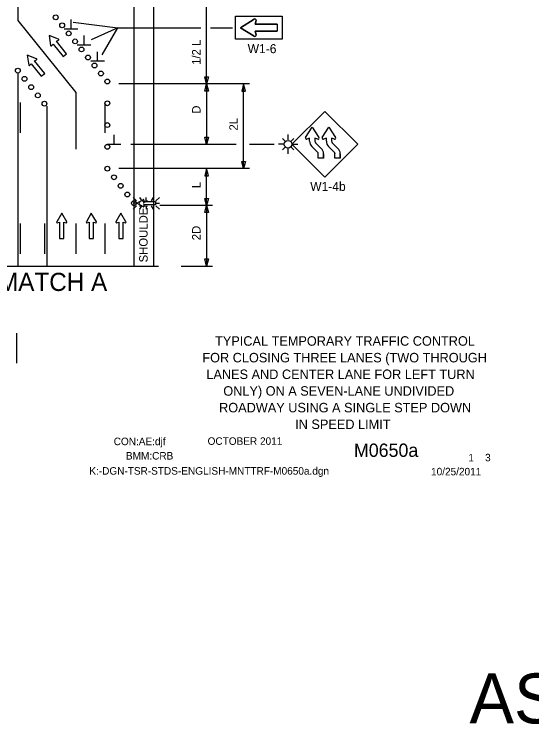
# Model space of a CAD drawing. Extents: x 16544 to 19504, y 5662 to 6909.
# Drawn here: x 17009 to 17436, y 5716 to 6314 of the extents above; entities that cross this region are included whole.
import ezdxf

# ---------------------------------------------------------------- set-up
doc = ezdxf.new("R2010")
doc.units = 0
for name, color, linetype in [('ALI_LEGAL_EX', 7, 'Continuous'), ('BORDER', 7, 'Continuous'), ('BORDER_SIGNAL_WO', 7, 'Continuous'), ('MT_SCRATCH_LEVEL_E', 7, 'Continuous'), ('PAVT_EDGE_EX', 7, 'Continuous'), ('TRAFFIC_SIGNS_PR', 7, 'Continuous'), ('TYPICAL_TEXT_DIMEN_PR', 7, 'Continuous')]:
    doc.layers.add(name, color=color, linetype=linetype)

msp = doc.modelspace()

# ---------------------------------------------------------------- linework, layer by layer
at = {"layer": 'ALI_LEGAL_EX'}
for points in [[(17013.46, 6241.23), (17013.46, 6216.23)], [(17083.46, 6241.23), (17083.46, 6216.23)], [(17013.46, 6141.23), (17013.46, 6116.23)], [(17033.46, 6141.23), (17033.46, 6116.23)], [(17059.46, 6141.23), (17059.46, 6116.23)], [(17083.46, 6141.23), (17083.46, 6116.23)]]:
    msp.add_lwpolyline(points, dxfattribs=at)
at = {"layer": 'MT_SCRATCH_LEVEL_E'}
for p, q in [((17037.27, 6296.58), (17038.61, 6288.36)), ((17045.04, 6293.54), (17037.27, 6296.58)), ((17037.27, 6296.58), (17038.61, 6288.36)), ((17045.04, 6293.54), (17037.27, 6296.58)), ((17039.41, 6288.13), (17040.6, 6289.49)), ((17039.41, 6288.13), (17040.6, 6289.49)), ((17040.6, 6289.49), (17048.91, 6279.16)), ((17040.6, 6289.49), (17048.91, 6279.16)), ((17043.51, 6291.83), (17045.09, 6292.7)), ((17043.51, 6291.83), (17045.09, 6292.7)), ((17051.83, 6281.51), (17043.51, 6291.83)), ((17051.83, 6281.51), (17043.51, 6291.83)), ((17019.13, 6280.37), (17020.47, 6272.15)), ((17026.9, 6277.33), (17019.13, 6280.37)), ((17019.13, 6280.37), (17020.47, 6272.15)), ((17026.9, 6277.33), (17019.13, 6280.37)), ((17025.37, 6275.62), (17026.95, 6276.49)), ((17025.37, 6275.62), (17026.95, 6276.49)), ((17048.91, 6279.16), (17051.83, 6281.51)), ((17048.91, 6279.16), (17051.83, 6281.51)), ((17021.27, 6271.92), (17022.46, 6273.28)), ((17021.27, 6271.92), (17022.46, 6273.28)), ((17022.46, 6273.28), (17030.77, 6262.95)), ((17022.46, 6273.28), (17030.77, 6262.95)), ((17033.69, 6265.3), (17025.37, 6275.62)), ((17033.69, 6265.3), (17025.37, 6275.62)), ((17030.77, 6262.95), (17033.69, 6265.3)), ((17030.77, 6262.95), (17033.69, 6265.3)), ((17047.7, 6149.79), (17043.59, 6142.55)), ((17047.7, 6149.79), (17043.59, 6142.55)), ((17051.85, 6142.55), (17047.7, 6149.79)), ((17051.85, 6142.55), (17047.7, 6149.79)), ((17072.2, 6149.79), (17068.09, 6142.55)), ((17072.2, 6149.79), (17068.09, 6142.55)), ((17076.35, 6142.55), (17072.2, 6149.79)), ((17076.35, 6142.55), (17072.2, 6149.79)), ((17096.7, 6149.79), (17092.59, 6142.55)), ((17096.7, 6149.79), (17092.59, 6142.55)), ((17100.84, 6142.55), (17096.7, 6149.79)), ((17100.84, 6142.55), (17096.7, 6149.79)), ((17044.07, 6141.87), (17045.85, 6142.19)), ((17044.07, 6141.87), (17045.85, 6142.19)), ((17045.85, 6142.19), (17045.85, 6128.93)), ((17045.85, 6142.19), (17045.85, 6128.93)), ((17049.59, 6128.93), (17049.59, 6142.19)), ((17049.59, 6142.19), (17051.37, 6141.87)), ((17049.59, 6128.93), (17049.59, 6142.19)), ((17049.59, 6142.19), (17051.37, 6141.87)), ((17068.57, 6141.87), (17070.35, 6142.19)), ((17068.57, 6141.87), (17070.35, 6142.19)), ((17070.35, 6142.19), (17070.35, 6128.93)), ((17070.35, 6142.19), (17070.35, 6128.93)), ((17074.09, 6128.93), (17074.09, 6142.19)), ((17074.09, 6142.19), (17075.87, 6141.87)), ((17074.09, 6128.93), (17074.09, 6142.19)), ((17074.09, 6142.19), (17075.87, 6141.87)), ((17093.07, 6141.87), (17094.85, 6142.19)), ((17093.07, 6141.87), (17094.85, 6142.19)), ((17094.85, 6142.19), (17094.85, 6128.93)), ((17094.85, 6142.19), (17094.85, 6128.93)), ((17098.59, 6128.93), (17098.59, 6142.19)), ((17098.59, 6142.19), (17100.36, 6141.87)), ((17098.59, 6128.93), (17098.59, 6142.19)), ((17098.59, 6142.19), (17100.36, 6141.87)), ((17045.85, 6128.93), (17049.59, 6128.93)), ((17045.85, 6128.93), (17049.59, 6128.93)), ((17070.35, 6128.93), (17074.09, 6128.93)), ((17070.35, 6128.93), (17074.09, 6128.93)), ((17094.85, 6128.93), (17098.59, 6128.93)), ((17094.85, 6128.93), (17098.59, 6128.93))]:
    msp.add_line(p, q, dxfattribs=at)
for centre, start, end in [((17039.06, 6288.44), 189.26563, 318.8046), ((17039.06, 6288.44), 189.26563, 318.8046), ((17044.86, 6293.11), 298.87699, 68.61391), ((17044.86, 6293.11), 298.87699, 68.61391), ((17026.72, 6276.9), 298.87699, 68.61391), ((17026.72, 6276.9), 298.87699, 68.61391), ((17020.92, 6272.23), 189.26563, 318.8046), ((17020.92, 6272.23), 189.26563, 318.8046), ((17044, 6142.33), 150.42484, 279.96381), ((17044, 6142.33), 150.42484, 279.96381), ((17051.44, 6142.33), 260.03619, 29.77312), ((17051.44, 6142.33), 260.03619, 29.77312), ((17068.5, 6142.33), 150.42484, 279.96381), ((17068.5, 6142.33), 150.42484, 279.96381), ((17075.94, 6142.33), 260.03619, 29.77312), ((17075.94, 6142.33), 260.03619, 29.77312), ((17092.99, 6142.33), 150.42484, 279.96381), ((17092.99, 6142.33), 150.42484, 279.96381), ((17100.43, 6142.33), 260.03619, 29.77312), ((17100.43, 6142.33), 260.03619, 29.77312)]:
    msp.add_arc(centre, 0.463, start, end, dxfattribs=at)
at = {"layer": 'PAVT_EDGE_EX'}
for p, q in [((17107.46, 6880.02), (17107.46, 6106.05)), ((17123.46, 6880.02), (17123.46, 6106.05)), ((17011.46, 6478.73), (17011.46, 6309.01)), ((17011.46, 6309.01), (17059.46, 6249.4)), ((17011.46, 6265.55), (17011.46, 6106.05)), ((17059.46, 6249.4), (17059.46, 6202.51)), ((17035.46, 6238.23), (17035.46, 6106.05))]:
    msp.add_line(p, q, dxfattribs=at)
msp.add_lwpolyline([(17010.78, 6025.74), (17010.78, 6050.74)], dxfattribs=at)
msp.add_lwpolyline([(17010.78, 6025.74), (17010.78, 6050.74)], dxfattribs=at)
at = {"layer": 'TRAFFIC_SIGNS_PR'}
for p, q in [((17206.63, 6310.11), (17195.47, 6303.01)), ((17207.48, 6305.81), (17208.31, 6308.87)), ((17225.87, 6305.81), (17207.48, 6305.81)), ((17225.87, 6305.81), (17225.87, 6300.21)), ((17195.47, 6303.01), (17206.63, 6295.9)), ((17208.31, 6297.15), (17207.48, 6300.21)), ((17207.48, 6300.21), (17225.87, 6300.21)), ((17237.98, 6206.75), (17265.14, 6233.9)), ((17265.14, 6233.9), (17292.29, 6206.75)), ((17232.32, 6209.26), (17230.21, 6211.37)), ((17234.83, 6210.31), (17234.83, 6214.81)), ((17237.34, 6209.26), (17239.45, 6211.37)), ((17231.68, 6206.75), (17226.84, 6206.75)), ((17232.32, 6204.24), (17230.21, 6202.13)), ((17237.34, 6204.24), (17239.45, 6202.13)), ((17237.98, 6206.75), (17242.87, 6206.75)), ((17265.14, 6179.6), (17237.98, 6206.75)), ((17259.16, 6200.23), (17254.44, 6204.95)), ((17259.15, 6200.23), (17254.44, 6204.95)), ((17262.21, 6203.28), (17257.49, 6208)), ((17257.49, 6208), (17262.21, 6203.28)), ((17292.29, 6206.75), (17265.14, 6179.6)), ((17272.95, 6200.23), (17268.24, 6204.95)), ((17272.95, 6200.23), (17268.24, 6204.95)), ((17276, 6203.28), (17271.29, 6208)), ((17271.29, 6208), (17276, 6203.28)), ((17234.83, 6198.78), (17234.83, 6203.2)), ((17259.76, 6195.16), (17259.76, 6198.86)), ((17264.07, 6195.16), (17264.07, 6198.86)), ((17273.55, 6195.16), (17273.55, 6198.86)), ((17277.87, 6195.16), (17277.87, 6198.86)), ((17264.07, 6195.16), (17259.76, 6195.16)), ((17277.87, 6195.16), (17273.55, 6195.16)), ((17106.65, 6162.79), (17109.47, 6159.97)), ((17112.08, 6162.79), (17113.29, 6160.7)), ((17117.55, 6159.97), (17117.55, 6162.79)), ((17123.34, 6162.79), (17121.71, 6159.97)), ((17125.64, 6159.97), (17128.46, 6162.8)), ((17109.47, 6157.94), (17106.65, 6157.94)), ((17125.64, 6157.94), (17128.46, 6157.94)), ((17106.65, 6153.09), (17109.47, 6155.91)), ((17113.37, 6155.28), (17112.11, 6153.09)), ((17117.55, 6155.91), (17117.55, 6153.09)), ((17121.69, 6155.91), (17123.32, 6153.09)), ((17125.64, 6155.91), (17128.46, 6153.09))]:
    msp.add_line(p, q, dxfattribs=at)
msp.add_lwpolyline([(17229.87, 6293.41), (17191.47, 6293.41), (17191.47, 6312.61), (17229.87, 6312.61)], close=True, dxfattribs=at)
for points in [[(17206.63, 6295.9), (17195.47, 6303.01), (17206.63, 6310.11)], [(17208.31, 6308.87), (17207.48, 6305.81), (17225.87, 6305.81), (17225.87, 6300.21), (17207.48, 6300.21), (17208.31, 6297.15)], [(17249.29, 6212.27), (17254.77, 6220.88), (17260.25, 6212.27)], [(17249.29, 6212.27), (17254.77, 6220.88), (17260.25, 6212.27)], [(17263.08, 6212.27), (17268.57, 6220.88), (17274.05, 6212.27)], [(17263.09, 6212.27), (17268.57, 6220.88), (17274.05, 6212.27)], [(17252.62, 6209.26), (17252.61, 6211.62), (17250.25, 6210.98)], [(17252.62, 6209.26), (17252.61, 6211.62), (17250.25, 6210.98)], [(17259.29, 6210.98), (17256.93, 6211.62), (17256.93, 6209.33)], [(17259.29, 6210.97), (17258.46, 6211.2), (17256.93, 6211.62), (17256.93, 6209.33)], [(17266.41, 6209.26), (17266.41, 6211.62), (17264.05, 6210.98)], [(17266.41, 6209.26), (17266.41, 6211.62), (17264.05, 6210.98)], [(17273.09, 6210.98), (17270.73, 6211.62), (17270.73, 6209.33)], [(17273.09, 6210.97), (17272.25, 6211.2), (17270.73, 6211.62), (17270.73, 6209.33)], [(17264.08, 6198.86), (17264.07, 6195.16), (17259.76, 6195.16), (17259.76, 6198.86)], [(17277.87, 6198.86), (17277.87, 6195.16), (17273.55, 6195.16), (17273.55, 6198.86)], [(17115.23, 6154.93), (17109.92, 6157.94), (17115.23, 6160.98)], [(17115.73, 6160.62), (17115.5, 6159.33), (17125.22, 6159.33), (17125.22, 6156.58), (17115.5, 6156.58), (17115.73, 6155.28)]]:
    msp.add_lwpolyline(points, dxfattribs=at)
for centre, radius in [((17042.79, 6311.55), 2), ((17048.13, 6304.93), 2), ((17053.46, 6298.31), 2), ((17058.79, 6291.68), 2), ((17064.13, 6285.06), 2), ((17069.46, 6278.43), 2), ((17074.79, 6271.81), 2), ((17011.46, 6267.55), 2), ((17080.13, 6265.19), 2), ((17016.96, 6260.72), 2), ((17085.46, 6258.56), 2), ((17022.46, 6253.89), 2), ((17027.96, 6247.06), 2), ((17033.46, 6240.23), 2), ((17085.46, 6240.56), 2), ((17085.46, 6222.56), 2), ((17085.46, 6204.56), 2), ((17234.83, 6206.75), 3.15), ((17085.46, 6186.56), 2), ((17090.96, 6179.43), 2), ((17096.45, 6172.3), 2), ((17101.95, 6165.18), 2), ((17107.45, 6158.05), 2)]:
    msp.add_circle(centre, radius, dxfattribs=at)
for centre, radius, start, end in [((17207.23, 6309.16), 1.12, 344.67308, 122.46963), ((17207.23, 6309.16), 1.12, 344.67308, 122.46962), ((17207.23, 6296.85), 1.12, 237.53038, 15.32692), ((17207.23, 6296.85), 1.12, 237.53038, 15.32692), ((17250.02, 6211.81), 0.866, 147.7292, 285.31719), ((17250.02, 6211.81), 0.866, 147.71964, 285.32011), ((17240.18, 6218.07), 10.8, 327.53351, 327.54311), ((17253.1, 6200.56), 10.8, 105.31922, 105.32004), ((17259.52, 6211.81), 0.864, 254.6014, 32.47956), ((17259.52, 6211.81), 0.866, 254.61481, 32.47119), ((17263.82, 6211.81), 0.866, 147.7292, 285.31719), ((17263.82, 6211.81), 0.866, 147.71964, 285.32011), ((17253.97, 6218.07), 10.8, 327.53351, 327.54311), ((17266.9, 6200.56), 10.8, 105.31922, 105.32004), ((17273.32, 6211.81), 0.864, 254.6014, 32.47956), ((17273.32, 6211.81), 0.866, 254.61481, 32.47119), ((17258.78, 6209.32), 6.17, 180.61811, 225.78746), ((17258.78, 6209.33), 6.17, 180.62445, 225.23128), ((17258.78, 6209.33), 1.85, 179.8762, 225.7877), ((17258.78, 6209.32), 1.85, 180, 225.78746), ((17272.58, 6209.32), 6.17, 180.61811, 225.78746), ((17272.58, 6209.33), 6.17, 180.62445, 225.23128), ((17272.58, 6209.33), 1.85, 179.8762, 225.7877), ((17272.58, 6209.32), 1.85, 180, 225.78746), ((17257.91, 6198.86), 1.85, 0, 47.62801), ((17257.91, 6198.86), 1.85, 0, 45.78746), ((17257.91, 6198.86), 6.17, 0, 45.78828), ((17257.91, 6198.86), 6.17, 0, 45.78746), ((17257.91, 6198.86), 6.17, 0, 45.78746), ((17271.7, 6198.86), 1.85, 0, 47.62801), ((17271.71, 6198.86), 1.85, 0, 45.78746), ((17271.71, 6198.86), 6.17, 0, 45.78746), ((17271.71, 6198.86), 6.17, 0, 45.78746), ((17271.7, 6198.86), 6.17, 0, 45.78828), ((17115.39, 6160.68), 0.341, 350.04067, 118.51671), ((17115.39, 6155.23), 0.341, 241.10835, 9.26922)]:
    msp.add_arc(centre, radius, start, end, dxfattribs=at)
at = {"layer": 'TYPICAL_TEXT_DIMEN_PR'}
for p, q in [((17167.46, 6256.56), (17167.46, 6320.18)), ((17055.51, 6301.87), (17055.51, 6309.65)), ((17057.09, 6307.51), (17094.03, 6302.79)), ((17061.13, 6301.87), (17049.88, 6301.87)), ((17094.03, 6302.79), (17072.11, 6292.85)), ((17081.04, 6280.64), (17094.03, 6302.79)), ((17094.03, 6302.79), (17162.62, 6302.79)), ((17170.74, 6302.79), (17188.76, 6302.79)), ((17066.17, 6288.65), (17066.17, 6296.44)), ((17071.8, 6288.65), (17060.55, 6288.65)), ((17077.34, 6275.33), (17077.34, 6283.12)), ((17082.97, 6275.33), (17071.72, 6275.33)), ((17167.46, 6256.56), (17165.89, 6262.43)), ((17165.89, 6262.43), (17167.46, 6262.43)), ((17167.46, 6262.43), (17169.03, 6262.43)), ((17169.03, 6262.43), (17167.46, 6256.56)), ((17203.04, 6256.56), (17094.92, 6256.56)), ((17172.46, 6256.56), (17134.08, 6256.56)), ((17165.89, 6250.7), (17167.46, 6256.56)), ((17167.46, 6256.56), (17167.46, 6206.56)), ((17167.46, 6256.56), (17169.03, 6250.7)), ((17198.04, 6256.56), (17196.47, 6250.7)), ((17198.04, 6186.56), (17198.04, 6256.56)), ((17199.61, 6250.7), (17198.04, 6256.56)), ((17167.46, 6250.7), (17165.89, 6250.7)), ((17169.03, 6250.7), (17167.46, 6250.7)), ((17196.47, 6250.7), (17198.04, 6250.7)), ((17198.04, 6250.7), (17199.61, 6250.7)), ((17090.97, 6206.56), (17090.97, 6214.35)), ((17167.46, 6206.56), (17165.89, 6212.43)), ((17165.89, 6212.43), (17167.46, 6212.43)), ((17167.46, 6212.43), (17169.03, 6212.43)), ((17169.03, 6212.43), (17167.46, 6206.56)), ((17096.59, 6206.56), (17085.34, 6206.56)), ((17191.85, 6206.56), (17104.96, 6206.56)), ((17223.26, 6206.56), (17203.04, 6206.56)), ((17198.04, 6186.56), (17196.47, 6192.43)), ((17196.47, 6192.43), (17198.04, 6192.43)), ((17198.04, 6192.43), (17199.61, 6192.43)), ((17199.61, 6192.43), (17198.04, 6186.56)), ((17203.04, 6186.56), (17094.92, 6186.56)), ((17167.46, 6186.56), (17165.89, 6180.7)), ((17167.46, 6156.05), (17167.46, 6186.56)), ((17169.03, 6180.7), (17167.46, 6186.56)), ((17165.89, 6180.7), (17167.46, 6180.7)), ((17167.46, 6180.7), (17169.03, 6180.7)), ((17167.46, 6156.05), (17165.89, 6161.91)), ((17165.89, 6161.91), (17167.46, 6161.91)), ((17167.46, 6161.91), (17169.03, 6161.91)), ((17169.03, 6161.91), (17167.46, 6156.05)), ((17172.46, 6156.05), (17128.9, 6156.05)), ((17165.89, 6150.19), (17167.46, 6156.05)), ((17167.46, 6150.19), (17165.89, 6150.19)), ((17167.46, 6156.05), (17169.03, 6150.19)), ((17167.46, 6156.05), (17167.46, 6106.05)), ((17169.03, 6150.19), (17167.46, 6150.19)), ((17167.46, 6106.05), (17165.89, 6111.91)), ((17165.89, 6111.91), (17167.46, 6111.91)), ((17167.46, 6111.91), (17169.03, 6111.91)), ((17169.03, 6111.91), (17167.46, 6106.05)), ((16919.16, 6106.05), (17127.76, 6106.05)), ((17011.46, 6106.05), (17035.46, 6106.05)), ((17011.46, 6106.05), (17035.46, 6106.05)), ((17146.46, 6106.05), (17172.46, 6106.05))]:
    msp.add_line(p, q, dxfattribs=at)

# ---------------------------------------------------------------- texts
at = {"layer": 'BORDER'}
for s, p in [('TYPICAL TEMPORARY TRAFFIC CONTROL', (17174.45, 6040.22)), ('FOR CLOSING THREE LANES (TWO THROUGH', (17163.95, 6026.46)), ('LANES AND CENTER LANE FOR LEFT TURN', (17167.28, 6012.7)), ('ONLY) ON A SEVEN-LANE UNDIVIDED', (17181.26, 5998.93)), ('ROADWAY USING A SINGLE STEP DOWN', (17177.78, 5985.17)), ('IN SPEED LIMIT', (17240.66, 5971.41))]:
    msp.add_text(s, height=7.8528, dxfattribs=at).set_placement(p)
at = {"layer": 'BORDER_SIGNAL_WO'}
for s, height, p in [('CON:AE:djf', 6.2, (17090.69, 5958.06)), ('    OCTOBER 2011    ', 6.2, (17159.08, 5958.34)), ('    M0650a   ', 11, (17272.86, 5948.38)), ('BMM:CRB   ', 6.2, (17100.81, 5946.17)), (' 1    3 ', 6.2, (17381.45, 5944.7)), ('K:-DGN-TSR-STDS-ENGLISH-MNTTRF-M0650a.dgn        ', 6.2, (17070.55, 5933.71)), ('10/25/2011    ', 6.2, (17352.93, 5933.13)), ('AS = 0.8 for Sign Cells', 41.2877, (17384.66, 5728.12))]:
    msp.add_text(s, height=height, dxfattribs=at).set_placement(p)
at = {"layer": 'TRAFFIC_SIGNS_PR'}
for s, p in [('W1-6', (17201.41, 6281.97)), ('W1-4b', (17253.09, 6168.16))]:
    msp.add_text(s, height=7.44, dxfattribs=at).set_placement(p)
at = {"layer": 'TYPICAL_TEXT_DIMEN_PR'}
for s, p in [('1/2 L', (17162.46, 6272.28)), ('D', (17162.46, 6231.93)), ('2L', (17193.21, 6218.05)), ('L', (17162.46, 6170.45)), ('SHOULDER', (17118.74, 6109.07)), ('2D', (17162.46, 6127.39))]:
    msp.add_text(s, height=7, rotation=90, dxfattribs=at).set_placement(p)
msp.add_text('A MATCH A', height=15, dxfattribs=at).set_placement((16976.13, 6085.48))

doc.saveas('drawing.dxf')
